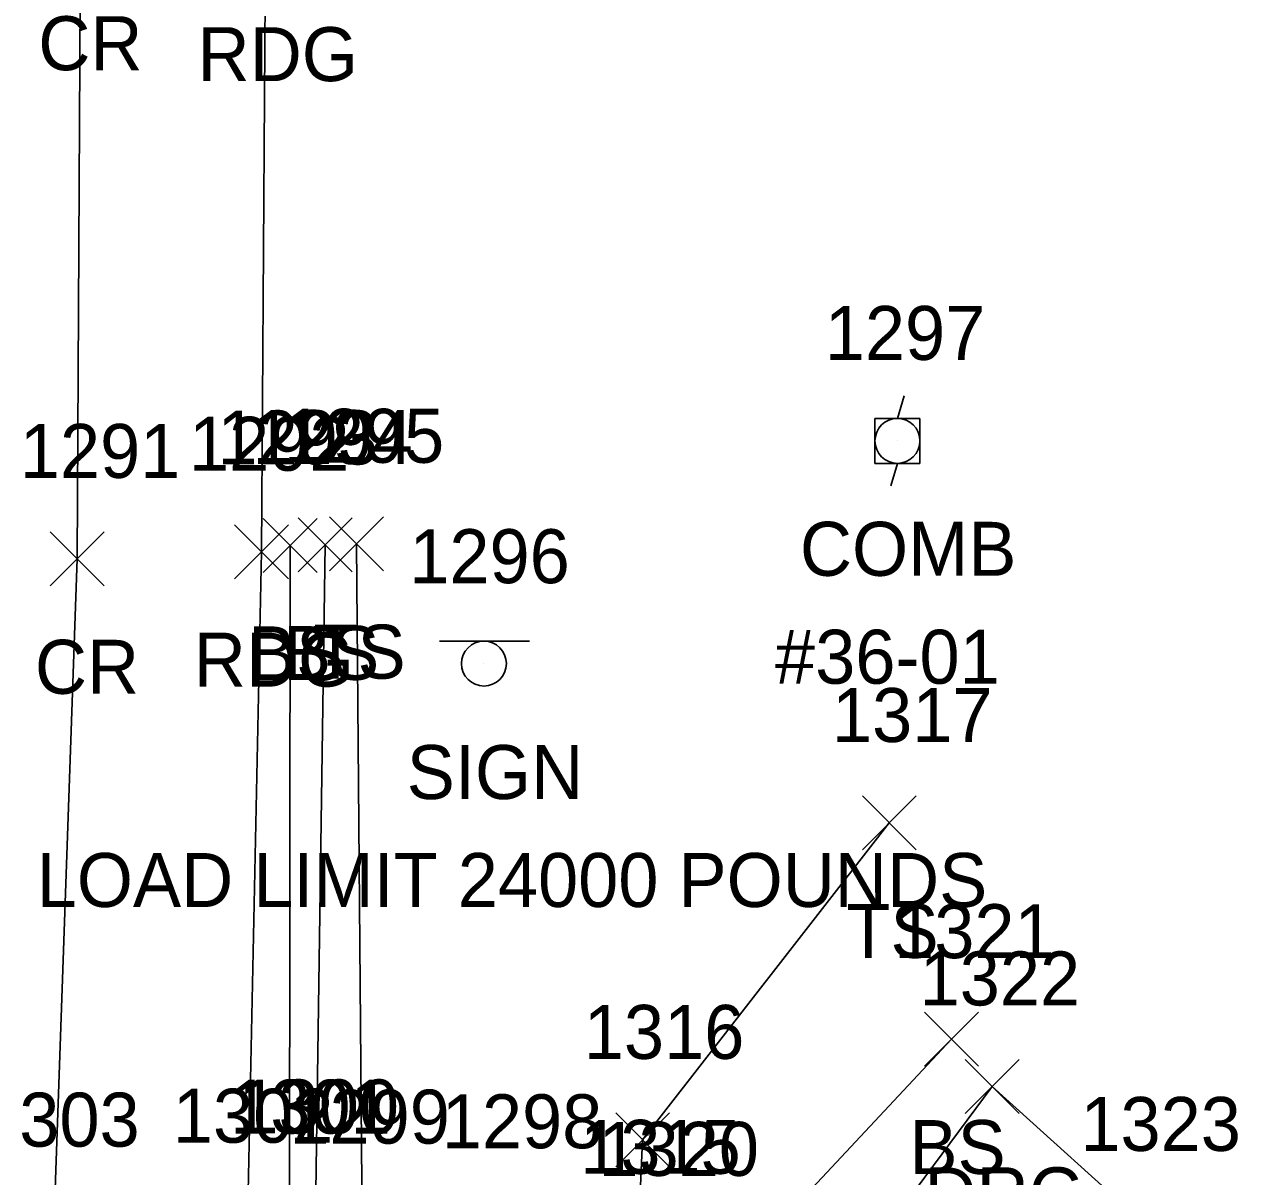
# Model space of a CAD drawing. Extents: x 1657482 to 1661439, y 647981 to 649041.
# Drawn here: x 1659805.99 to 1659850.96, y 648182.25 to 648224.96 of the extents above; entities that cross this region are included whole.
import ezdxf

# ---------------------------------------------------------------- set-up
doc = ezdxf.new("R2010")
doc.units = 0
for name, color, linetype in [('L_A', 7, 'Continuous'), ('L_I', 7, 'Continuous'), ('L_TIC', 7, 'Continuous'), ('LELB', 7, 'Continuous'), ('P_A', 7, 'Continuous'), ('P_I', 7, 'Continuous'), ('P_TIC', 7, 'Continuous'), ('PEU', 7, 'Continuous'), ('PRC', 7, 'Continuous'), ('R_A', 7, 'Continuous'), ('R_I', 7, 'Continuous'), ('R_TIC', 7, 'Continuous'), ('RDG', 7, 'Continuous'), ('S_A', 7, 'Continuous'), ('S_C', 7, 'Continuous'), ('S_I', 7, 'Continuous'), ('SSGN', 7, 'Continuous'), ('U_A', 7, 'Continuous'), ('U_C', 7, 'Continuous'), ('U_I', 7, 'Continuous'), ('UP', 7, 'Continuous')]:
    doc.layers.add(name, color=color, linetype=linetype)

msp = doc.modelspace()

# ---------------------------------------------------------------- linework, layer by layer
at = {"layer": 'L_TIC'}
for points in [[(1659814.839, 648204.649), (1659816.839, 648206.649)], [(1659816.839, 648204.649), (1659814.839, 648206.649)], [(1659816.135, 648204.667), (1659818.135, 648206.667)], [(1659818.135, 648204.667), (1659816.135, 648206.667)], [(1659817.296, 648204.712), (1659819.296, 648206.712)], [(1659819.296, 648204.712), (1659817.296, 648206.712)], [(1659837.047, 648194.363), (1659839.047, 648196.363)], [(1659839.047, 648194.363), (1659837.047, 648196.363)], [(1659839.35, 648186.353), (1659841.35, 648188.353)], [(1659841.35, 648186.353), (1659839.35, 648188.353)], [(1659827.906, 648182.62), (1659829.906, 648184.62)], [(1659829.906, 648182.62), (1659827.906, 648184.62)]]:
    msp.add_lwpolyline(points, dxfattribs=at)
at = {"layer": 'LELB'}
for points in [[(1659815.839, 648205.649), (1659815.824, 648180.85), (1659817.477, 648160.333), (1659819.862, 648143.017), (1659820.895, 648130.299), (1659824.063, 648128.86), (1659827.949, 648129.135)], [(1659817.135, 648205.667), (1659816.785, 648180.856), (1659817.477, 648160.333)], [(1659818.296, 648205.712), (1659818.513, 648180.48), (1659819.139, 648164.418), (1659818.624, 648162.174), (1659819.118, 648160.547), (1659823.473, 648146.991), (1659821.369, 648140.573), (1659822.05, 648135.189), (1659825.728, 648132.378)], [(1659828.715, 648179.361), (1659828.906, 648183.62), (1659838.047, 648195.363)], [(1659826.31, 648172.334), (1659840.35, 648187.353)]]:
    msp.add_lwpolyline(points, dxfattribs=at)
at = {"layer": 'P_TIC'}
for points in [[(1659813.784, 648204.417), (1659815.784, 648206.417)], [(1659815.784, 648204.417), (1659813.784, 648206.417)], [(1659806.949, 648204.151), (1659808.949, 648206.151)], [(1659808.949, 648204.151), (1659806.949, 648206.151)]]:
    msp.add_lwpolyline(points, dxfattribs=at)
at = {"layer": 'PEU'}
msp.add_lwpolyline([(1659815.505, 648322.818), (1659814.949, 648287.397), (1659814.827, 648255.089), (1659814.923, 648227.856), (1659814.784, 648205.417), (1659814.267, 648180.513), (1659814.091, 648160.024), (1659817.14, 648140.384), (1659817.844, 648129.177), (1659822.063, 648119.729)], dxfattribs=at)
at = {"layer": 'PRC'}
msp.add_lwpolyline([(1659807.215, 648322.663), (1659808.086, 648286.107), (1659808.383, 648256.053), (1659808.075, 648228.261), (1659807.949, 648205.151), (1659807.089, 648180.369), (1659807.153, 648158.514), (1659808.358, 648139.109), (1659809.074, 648120.362)], dxfattribs=at)
at = {"layer": 'R_TIC'}
for points in [[(1659840.86, 648184.601), (1659842.86, 648186.601)], [(1659842.86, 648184.601), (1659840.86, 648186.601)]]:
    msp.add_lwpolyline(points, dxfattribs=at)
at = {"layer": 'RDG'}
msp.add_lwpolyline([(1659814.091, 648160.024), (1659817.477, 648160.333), (1659819.118, 648160.547), (1659823.273, 648161.459), (1659827.285, 648165.972), (1659841.86, 648185.601), (1659847.819, 648180.209)], dxfattribs=at)
at = {"layer": 'SSGN'}
for p, q in [((1659821.377, 648202.104), (1659824.71, 648202.104)), ((1659823.023, 648201.27), (1659823.023, 648201.27))]:
    msp.add_line(p, q, dxfattribs=at)
msp.add_circle((1659823.023, 648201.27), 0.833, dxfattribs=at)
at = {"layer": 'UP'}
for p, q in [((1659838.597, 648211.191), (1659838.347, 648210.358)), ((1659837.514, 648208.691), (1659837.514, 648210.358)), ((1659837.514, 648210.358), (1659839.18, 648210.358)), ((1659839.18, 648210.358), (1659839.18, 648208.691)), ((1659838.347, 648209.524), (1659838.347, 648209.524)), ((1659839.18, 648208.691), (1659837.514, 648208.691)), ((1659838.097, 648207.858), (1659838.347, 648208.691))]:
    msp.add_line(p, q, dxfattribs=at)
msp.add_circle((1659838.347, 648209.524), 0.833, dxfattribs=at)

# ---------------------------------------------------------------- texts
at = {"layer": 'L_A'}
for s, p in [('BS', (1659814.28, 648200.649)), ('BS', (1659815.576, 648200.667)), ('TS', (1659816.705, 648200.712)), ('TS', (1659836.456, 648190.363)), ('BS', (1659838.791, 648182.353))]:
    msp.add_text(s, height=2, dxfattribs=at).set_placement(p)
at = {"layer": 'L_I'}
for s, p in [('1293', (1659813.146, 648208.649)), ('1294', (1659814.442, 648208.667)), ('1295', (1659815.603, 648208.712)), ('1317', (1659835.921, 648198.363)), ('1321', (1659838.225, 648190.353)), ('1316', (1659826.725, 648186.62)), ('1301', (1659813.619, 648183.85)), ('1300', (1659813.927, 648183.856)), ('1299', (1659815.813, 648183.48)), ('1298', (1659821.462, 648183.307)), ('1315', (1659826.59, 648182.361)), ('1315', (1659826.59, 648182.361)), ('1320', (1659827.267, 648182.285))]:
    msp.add_text(s, height=2, dxfattribs=at).set_placement(p)
at = {"layer": 'P_A'}
for s, p in [('CR', (1659806.508, 648223.261)), ('RDG', (1659812.411, 648222.856)), ('RDG', (1659812.272, 648200.417)), ('CR', (1659806.383, 648200.151))]:
    msp.add_text(s, height=2, dxfattribs=at).set_placement(p)
at = {"layer": 'P_I'}
for s, p in [('1292', (1659812.091, 648208.417)), ('1291', (1659805.824, 648208.151)), ('1303', (1659804.318, 648183.369)), ('1302', (1659811.496, 648183.513))]:
    msp.add_text(s, height=2, dxfattribs=at).set_placement(p)
at = {"layer": 'R_A'}
msp.add_text('DRG', height=2, dxfattribs=at).set_placement((1659839.348, 648180.601))
at = {"layer": 'R_I'}
for s, p in [('1322', (1659839.168, 648188.601)), ('1323', (1659845.126, 648183.209))]:
    msp.add_text(s, height=2, dxfattribs=at).set_placement(p)
at = {"layer": 'S_A'}
msp.add_text('SIGN', height=2, dxfattribs=at).set_placement((1659820.162, 648196.25))
at = {"layer": 'S_C'}
msp.add_text('LEGAL LOAD LIMIT 24000 POUNDS', height=2, dxfattribs=at).set_placement((1659797.084, 648192.25))
at = {"layer": 'S_I'}
msp.add_text('1296', height=2, dxfattribs=at).set_placement((1659820.256, 648204.25))
at = {"layer": 'U_A'}
msp.add_text('COMB', height=2, dxfattribs=at).set_placement((1659834.733, 648204.524))
at = {"layer": 'U_C'}
msp.add_text('#36-01', height=2, dxfattribs=at).set_placement((1659833.812, 648200.524))
at = {"layer": 'U_I'}
msp.add_text('1297', height=2, dxfattribs=at).set_placement((1659835.654, 648212.524))

doc.saveas('drawing.dxf')
